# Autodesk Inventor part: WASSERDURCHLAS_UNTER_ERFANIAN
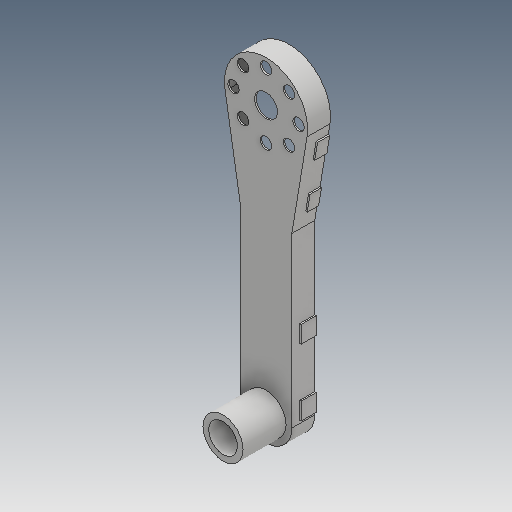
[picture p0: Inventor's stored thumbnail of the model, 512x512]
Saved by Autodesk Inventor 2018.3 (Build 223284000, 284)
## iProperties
Created: 2019-01
Part Number: WASSERDURCHLAS_UNTER_ERFANIAN
Material: Generisch
Document SubType Name: Modeling
Designer: zand
Density: 1 g/cm^3
Appearance: Vorgabe
Mass: 3.28262 g
Surface Area: 95.819 cm^2
Volume: 3.28262 cm^3
Author: zand
Revision Number: 16LAST_VERSION
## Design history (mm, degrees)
feature "Basis1"
node "Volumenkörper1"
